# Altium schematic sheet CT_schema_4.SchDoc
size 251 x 159 mm
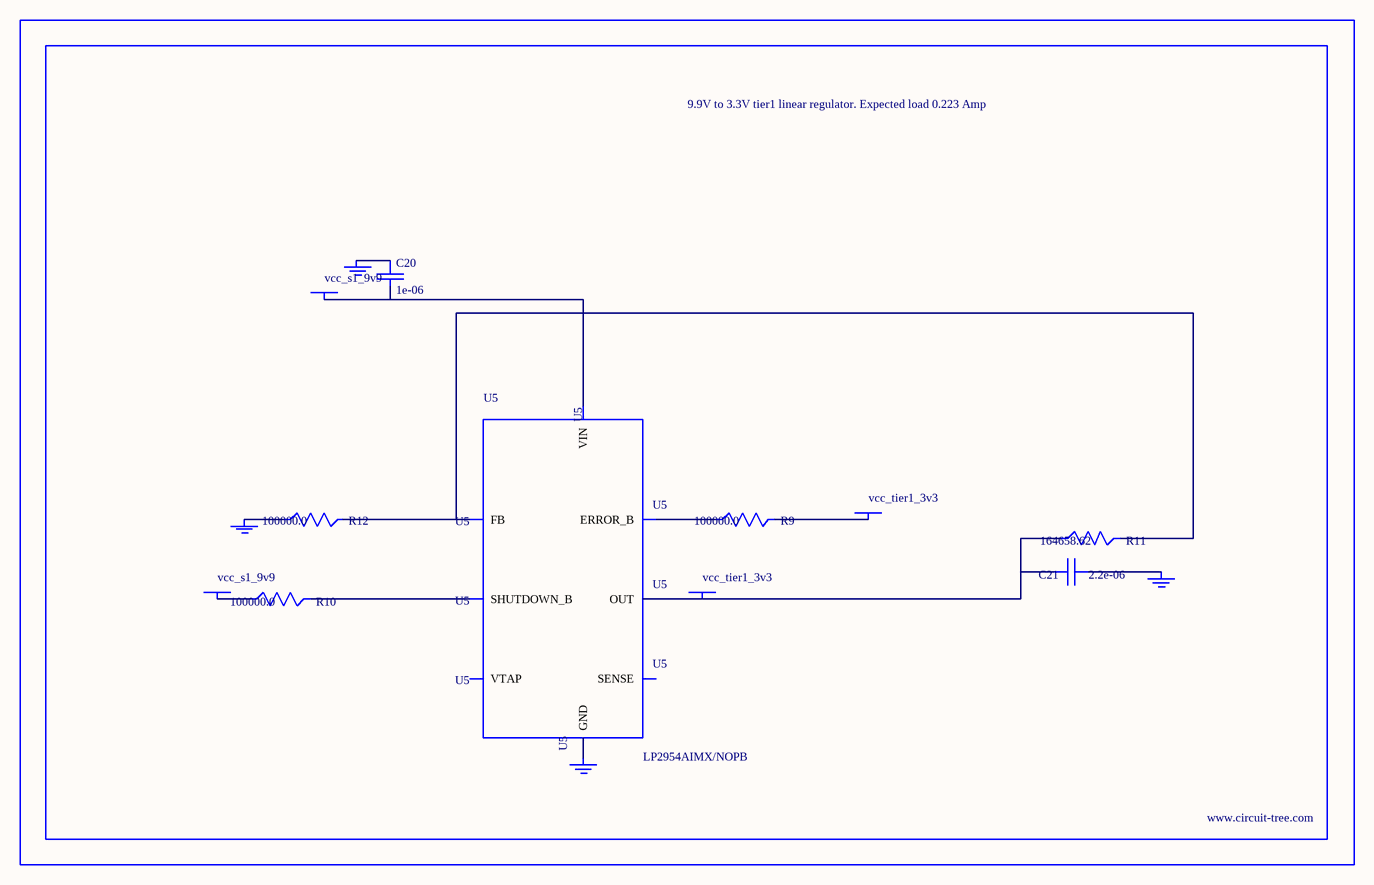
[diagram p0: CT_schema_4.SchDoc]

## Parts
BORDER3  (no value)
C20  1e-06  [EXV-9B]
C21  2.2e-06  [EXV-9B]
GND_INSTANCE_3_0  (no value)
GND_INSTANCE_3_1  (no value)
GND_INSTANCE_3_2  (no value)
GND_INSTANCE_3_3  (no value)
POWER_INSTANCE_3_0  vcc_s1_9v9
POWER_INSTANCE_3_1  vcc_tier1_3v3
POWER_INSTANCE_3_2  vcc_s1_9v9
POWER_INSTANCE_3_3  vcc_tier1_3v3
R9  100000.0  [R0603]
R10  100000.0  [R0603]
R11  164658.62  [R0603]
R12  100000.0  [R0603]
U5  LP2954AIMX/NOPB  [LP2954]

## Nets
NetC20_1: C20.1 GND_INSTANCE_3_2.0(GND)
NetC20_2: C20.2 POWER_INSTANCE_3_2.0(PWR) U5.8(VIN)
NetC21_1: C21.1 GND_INSTANCE_3_0.0(GND)
NetC21_2: C21.2 POWER_INSTANCE_3_3.0(PWR) R11.1 U5.1(OUT)
NetGND_INSTANCE_3_1_0: GND_INSTANCE_3_1.0(GND) R12.1
NetGND_INSTANCE_3_3_0: GND_INSTANCE_3_3.0(GND) U5.4(GND)
NetPOWER_INSTANCE_3_0_0: POWER_INSTANCE_3_0.0(PWR) R10.1
NetPOWER_INSTANCE_3_1_0: POWER_INSTANCE_3_1.0(PWR) R9.2
NetR9_1: R9.1 U5.5(ERROR_B)
NetR10_2: R10.2 U5.3(SHUTDOWN_B)
NetR11_2: R11.2 R12.2 U5.7(FB)

Not connected (* = marked no-connect by the designer): U5 2(SENSE) 6(VTAP)

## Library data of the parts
BORDER3 = BORDER_PAGE3
C20 = EDK105M050A9BAA
C21 = EDK225M050A9BAA
GND_INSTANCE_3_0-GND_INSTANCE_3_3 = GND
POWER_INSTANCE_3_0-POWER_INSTANCE_3_3 = PWR
R9 R10 R12 = RC0603JR-07100KL
R11 = R11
